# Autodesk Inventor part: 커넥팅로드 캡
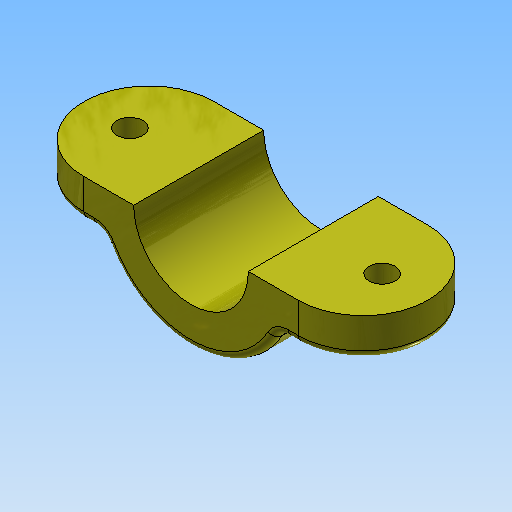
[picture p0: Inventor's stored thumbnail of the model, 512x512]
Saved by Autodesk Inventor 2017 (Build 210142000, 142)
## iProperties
Created: 2017-05
Part Number: 커넥팅로드 캡
Material: 강철, 탄소
Document SubType Name: Modeling
Designer: mduedu
Density: 7.87 g/cm^3
Mass: 31.5627 g
Surface Area: 22.8316 cm^2
Volume: 4.0105 cm^3
Appearance: 노란색
Author: mduedu
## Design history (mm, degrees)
sketch "스케치1"
  geometry: L1 (22.5, 0)-(22.5, -5); L2 (-22.5, -5)-(-22.5, 0); L3 (-22.5, 0)-(-7.5, 0); L4 (7.5, 0)-(22.5, 0); L5 (22.5, -5)-(11.456, -5); L6 (-11.456, -5)-(-22.5, -5); A1 r 7.5 centre (0, 0) between (-7.5, 0) and (7.5, 0); A2 r 12.5 centre (0, 0) between (-11.456, -5) and (11.456, -5); 2 further points
  constraints: 12 end point, 5 parallel, 4 point on circle, 3 coincident, 2 centre point, 2 collinear, 2 horizontal, 2 horizontal alignment, 2 perpendicular
  dimensions: "d0" = 45 distance of L2.end L1.start; "d2" = 5 distance of L2.start L2.end; "d3" = 15 diameter of A1; "d4" = 25 diameter of A2
extrude "돌출1" new body sketch "스케치1" stored distance "d5" = 17; taper "d6" = 0 deg
fillet "모깎기1"
fillet "모깎기2"
fillet "모깎기3" dims "d11" = 2
fillet "모깎기4" dims "d12" = 1
sketch "스케치4"
  geometry: 2 further points
  constraints: 2 other
hole "구멍1" sketch "스케치4" at (30.5, 7.5), (-2.5, 7.5) diameter "d19" = 3.4; stored, may be unused: countersink angle "d23" = 90 deg, drill point angle "d25" = 0 deg; dims "d20" = 6, "d21" = 4, "d22" = 2, "d24" = 8
node "솔리드1"
